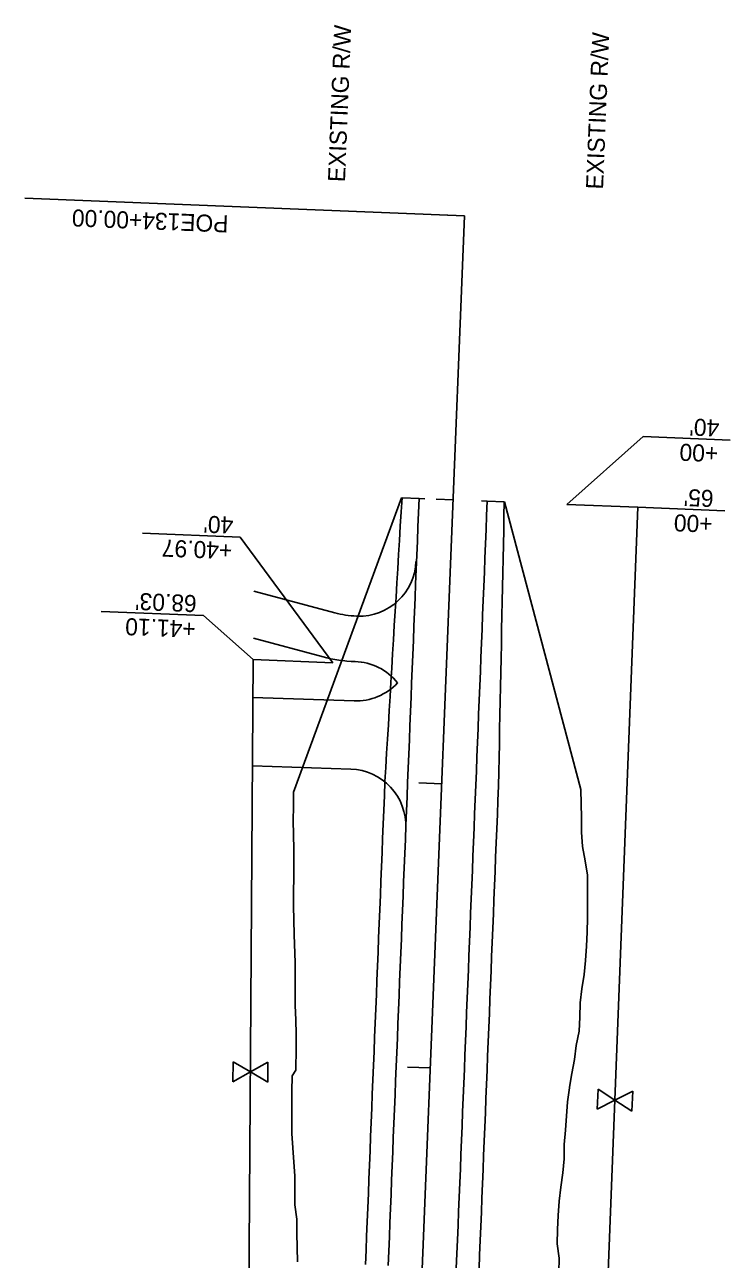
# Model space of a CAD drawing. Extents: x 634057 to 641016, y 287858 to 292331.
# Drawn here: x 634188.6 to 634436.9, y 291897 to 292331.3 of the extents above; entities that cross this region are included whole.
import ezdxf

# ---------------------------------------------------------------- set-up
doc = ezdxf.new("R2010")
doc.units = 0
for name, color, linetype in [('53', 7, 'Continuous'), ('R_50 Horz Alg PC PI PT', 7, 'Continuous'), ('R_50 Horz Alg Ticks', 7, 'Continuous'), ('R_Drive', 7, 'Continuous'), ('R_Horz Alg', 7, 'Continuous'), ('R_No Plot', 7, 'Continuous'), ('R_Proposed Const Limits', 7, 'Continuous'), ('R_Proposed Road', 7, 'Continuous'), ('R_Proposed Shoulder', 7, 'Continuous'), ('R_ROW', 7, 'Continuous')]:
    doc.layers.add(name, color=color, linetype=linetype)

msp = doc.modelspace()

# ---------------------------------------------------------------- linework, layer by layer
at = {"layer": '53'}
for p, q in [((634436.9, 292185.14), (634406.28, 292186.38)), ((634434.92, 292160.33), (634404.32, 292161.54)), ((634264.41, 292151.03), (634230.05, 292152.41)), ((634251.52, 292123.41), (634215.51, 292124.86))]:
    msp.add_line(p, q, dxfattribs=at)
for points in [[(634406.28, 292186.38), (634379.34, 292162.55)], [(634264.41, 292151.03), (634297.03, 292106.77)], [(634251.52, 292123.41), (634269.02, 292108.03)]]:
    msp.add_lwpolyline(points, dxfattribs=at)
at = {"layer": 'R_50 Horz Alg PC PI PT'}
msp.add_lwpolyline([(634343.4, 292264.06), (634188.6, 292270.3)], dxfattribs=at)
at = {"layer": 'R_50 Horz Alg Ticks'}
for points in [[(634337.38, 292264.32), (634343.37, 292264.08)], [(634333.35, 292164.4), (634339.35, 292164.16)], [(634327.35, 292064.55), (634335.35, 292064.22)], [(634323.33, 291964.63), (634331.32, 291964.31)]]:
    msp.add_lwpolyline(points, dxfattribs=at)
at = {"layer": 'R_Drive'}
for p, q in [((634297.72, 292124.39), (634269.19, 292132.04)), ((634305.63, 292123.24), (634305.4, 292123.25)), ((634293.58, 292108.93), (634269.07, 292115.5)), ((634304.51, 292093.41), (634268.93, 292094.58)), ((634303.38, 292069.43), (634268.76, 292070.57))]:
    msp.add_line(p, q, dxfattribs=at)
for centre, radius, start, end in [((634306.29, 292143.23), 20, 268.0998, 357.8615), ((634306.52, 292157.23), 34, 254.9972, 268.0998), ((634306.52, 292157.23), 50, 254.9972, 268.0998), ((634304.2, 292087.27), 20, 38.6845, 88.0998), ((634305.17, 292113.4), 20, 268.1082, 317.0537), ((634302.72, 292049.44), 20, 357.8615, 88.1082)]:
    msp.add_arc(centre, radius, start, end, dxfattribs=at)
at = {"layer": 'R_Horz Alg'}
msp.add_line((634328.23, 291887.62), (634343.4, 292264.06), dxfattribs=at)
at = {"layer": 'R_Proposed Const Limits'}
for points in [[(634283.19, 292061.32), (634321.19, 292164.86)], [(634357.49, 292163.4), (634384.25, 292062.26)], [(634384.25, 292062.26), (634384.49, 292052.24), (634384.49, 292047.23), (634384.92, 292042.21), (634385.8, 292037.17), (634386.62, 292032.14), (634386.69, 292027.13), (634386.67, 292022.12), (634386.63, 292017.12), (634386.54, 292012.12), (634386.33, 292007.13), (634385.91, 292002.14), (634385.5, 291997.15), (634384.64, 291992.18), (634384.07, 291987.2), (634383.96, 291982.2), (634383.75, 291977.21), (634382.63, 291972.25), (634382.04, 291967.27), (634381.11, 291962.3), (634380.34, 291957.6)], [(634283.99, 291963.49), (634284.08, 291971.21), (634284.11, 291976.22), (634284.06, 291981.22), (634283.72, 291986.24), (634283.73, 291996.25), (634283.74, 292001.25), (634283.46, 292011.27), (634283.26, 292016.28), (634283.14, 292021.29), (634283.24, 292026.29), (634283.28, 292031.29), (634283.32, 292041.3), (634283.23, 292046.31), (634283.1, 292051.32), (634283.14, 292056.32), (634283.19, 292061.32)], [(634284.56, 291896.13), (634284.47, 291901.14), (634284.35, 291906.15), (634284.39, 291911.15), (634283.68, 291916.18), (634283.62, 291921.19), (634283.7, 291926.19), (634283, 291936.23), (634282.63, 291941.25), (634282.61, 291946.25), (634282.66, 291956.26), (634282.72, 291961.26), (634282.73, 291961.52), (634282.73, 291961.53), (634283.99, 291963.49)], [(634380.34, 291957.6), (634380.3, 291957.33), (634379.61, 291952.35), (634378.9, 291942.37), (634378.45, 291937.39), (634378.48, 291932.38), (634377.91, 291927.4), (634377.22, 291922.42), (634376.72, 291917.44), (634376.37, 291912.45), (634376.05, 291907.46), (634376.01, 291902.46), (634376.65, 291897.43), (634376.58, 291892.43)]]:
    msp.add_lwpolyline(points, dxfattribs=at)
at = {"layer": 'R_Proposed Road'}
for points in [[(634316.51, 291894.85), (634316.71, 291899.84), (634316.92, 291904.84), (634317.12, 291909.83), (634317.32, 291914.83), (634317.52, 291919.83), (634317.72, 291924.82), (634317.92, 291929.82), (634318.12, 291934.81), (634318.32, 291939.81), (634318.53, 291944.81), (634318.73, 291949.8), (634318.93, 291954.8), (634319.13, 291959.79), (634319.33, 291964.79), (634319.53, 291969.78), (634319.73, 291974.78), (634319.93, 291979.78), (634320.14, 291984.77), (634320.34, 291989.77), (634320.54, 291994.76), (634320.74, 291999.76), (634320.94, 292004.76), (634321.14, 292009.75), (634321.34, 292014.75), (634321.54, 292019.74), (634321.75, 292024.74), (634321.95, 292029.74), (634322.15, 292034.73), (634322.35, 292039.73), (634322.55, 292044.72), (634322.75, 292049.72), (634322.95, 292054.72), (634323.15, 292059.71), (634323.36, 292064.71), (634323.56, 292069.7), (634323.76, 292074.7), (634323.96, 292079.7), (634324.16, 292084.69), (634324.36, 292089.69), (634324.56, 292094.68), (634324.76, 292099.68), (634324.97, 292104.68), (634325.17, 292109.67), (634325.37, 292114.67), (634325.57, 292119.66), (634325.77, 292124.66), (634325.97, 292129.66), (634326.17, 292134.65), (634326.37, 292139.65), (634326.58, 292144.64), (634326.78, 292149.64), (634326.98, 292154.63), (634327.18, 292159.63), (634327.38, 292164.63), (634329.38, 292164.55)], [(634340.49, 291893.88), (634340.69, 291898.88), (634340.9, 291903.87), (634341.1, 291908.87), (634341.3, 291913.86), (634341.5, 291918.86), (634341.7, 291923.86), (634341.9, 291928.85), (634342.1, 291933.85), (634342.3, 291938.84), (634342.51, 291943.84), (634342.71, 291948.84), (634342.91, 291953.83), (634343.11, 291958.83), (634343.31, 291963.82), (634343.51, 291968.82), (634343.71, 291973.81), (634343.91, 291978.81), (634344.12, 291983.81), (634344.32, 291988.8), (634344.52, 291993.8), (634344.72, 291998.79), (634344.92, 292003.79), (634345.12, 292008.79), (634345.32, 292013.78), (634345.52, 292018.78), (634345.73, 292023.77), (634345.93, 292028.77), (634346.13, 292033.77), (634346.33, 292038.76), (634346.53, 292043.76), (634346.73, 292048.75), (634346.93, 292053.75), (634347.13, 292058.75), (634347.34, 292063.74), (634347.54, 292068.74), (634347.74, 292073.73), (634347.94, 292078.73), (634348.14, 292083.73), (634348.34, 292088.72), (634348.54, 292093.72), (634348.74, 292098.71), (634348.95, 292103.71), (634349.15, 292108.71), (634349.35, 292113.7), (634349.55, 292118.7), (634349.75, 292123.69), (634349.95, 292128.69), (634350.15, 292133.69), (634350.35, 292138.68), (634350.56, 292143.68), (634350.76, 292148.67), (634350.96, 292153.67), (634351.16, 292158.66), (634351.36, 292163.66), (634349.36, 292163.74)]]:
    msp.add_lwpolyline(points, dxfattribs=at)
at = {"layer": 'R_Proposed Shoulder'}
for points in [[(634308.52, 291895.17), (634308.72, 291900.16), (634308.92, 291905.16), (634309.12, 291910.16), (634309.32, 291915.15), (634309.53, 291920.15), (634309.73, 291925.14), (634309.93, 291930.14), (634310.13, 291935.14), (634310.33, 291940.13), (634310.53, 291945.13), (634310.73, 291950.12), (634310.93, 291955.12), (634311.14, 291960.11), (634311.34, 291965.11), (634311.54, 291970.11), (634311.74, 291975.1), (634311.94, 291980.1), (634312.14, 291985.09), (634312.34, 291990.09), (634312.54, 291995.09), (634312.75, 292000.08), (634312.95, 292005.08), (634313.15, 292010.07), (634313.35, 292015.07), (634313.55, 292020.07), (634313.75, 292025.06), (634313.95, 292030.06), (634314.15, 292035.05), (634314.36, 292040.05), (634314.56, 292045.05), (634314.76, 292050.04), (634314.96, 292055.04), (634315.16, 292060.03), (634315.36, 292065.03), (634315.66, 292070.02), (634315.96, 292075.01), (634316.27, 292080.01), (634316.57, 292085), (634316.87, 292089.99), (634317.17, 292094.98), (634317.47, 292099.97), (634317.77, 292104.97), (634318.07, 292109.96), (634318.37, 292114.95), (634318.67, 292119.94), (634318.98, 292124.93), (634319.28, 292129.92), (634319.58, 292134.92), (634319.88, 292139.91), (634320.18, 292144.9), (634320.48, 292149.89), (634320.78, 292154.88), (634321.08, 292159.88), (634321.38, 292164.87), (634327.38, 292164.63)], [(634348.49, 291893.56), (634348.69, 291898.55), (634348.89, 291903.55), (634349.09, 291908.55), (634349.29, 291913.54), (634349.49, 291918.54), (634349.69, 291923.53), (634349.9, 291928.53), (634350.1, 291933.53), (634350.3, 291938.52), (634350.5, 291943.52), (634350.7, 291948.51), (634350.9, 291953.51), (634351.1, 291958.5), (634351.3, 291963.5), (634351.51, 291968.5), (634351.71, 291973.49), (634351.91, 291978.49), (634352.11, 291983.48), (634352.31, 291988.48), (634352.51, 291993.48), (634352.71, 291998.47), (634352.91, 292003.47), (634353.12, 292008.46), (634353.32, 292013.46), (634353.52, 292018.46), (634353.72, 292023.45), (634353.92, 292028.45), (634354.12, 292033.44), (634354.32, 292038.44), (634354.52, 292043.44), (634354.73, 292048.43), (634354.93, 292053.43), (634355.13, 292058.42), (634355.33, 292063.42), (634355.43, 292068.42), (634355.53, 292073.42), (634355.63, 292078.42), (634355.73, 292083.42), (634355.84, 292088.42), (634355.94, 292093.42), (634356.04, 292098.42), (634356.14, 292103.42), (634356.24, 292108.42), (634356.34, 292113.42), (634356.44, 292118.42), (634356.55, 292123.42), (634356.65, 292128.42), (634356.75, 292133.42), (634356.85, 292138.42), (634356.95, 292143.42), (634357.05, 292148.42), (634357.15, 292153.42), (634357.25, 292158.42), (634357.36, 292163.42), (634351.36, 292163.66)]]:
    msp.add_lwpolyline(points, dxfattribs=at)
at = {"layer": 'R_ROW'}
for p, q in [((634269.02, 292108.03), (634297.03, 292106.77)), ((634261.87, 291959.42), (634261.92, 291966.49)), ((634261.92, 291966.49), (634268.02, 291962.91)), ((634268.02, 291962.91), (634274.17, 291966.39)), ((634274.17, 291966.39), (634274.11, 291959.32)), ((634268.02, 291962.91), (634261.87, 291959.42)), ((634274.11, 291959.32), (634268.02, 291962.91)), ((634389.99, 291949.75), (634390.36, 291956.81)), ((634396.29, 291952.96), (634389.99, 291949.75)), ((634390.36, 291956.81), (634396.29, 291952.96)), ((634396.29, 291952.96), (634402.59, 291956.16)), ((634402.22, 291949.1), (634396.29, 291952.96)), ((634402.59, 291956.16), (634402.22, 291949.1))]:
    msp.add_line(p, q, dxfattribs=at)
for points in [[(634379.34, 292162.55), (634404.32, 292161.54)], [(634404.32, 292161.54), (634388.9, 291762.53), (634380.33, 291604.07)], [(634269.02, 292108.03), (634267.36, 291866.68), (634250.58, 291620.66)]]:
    msp.add_lwpolyline(points, dxfattribs=at)

# ---------------------------------------------------------------- texts
at = {"layer": '53'}
for s, rotation, p in [('EXISTING R/W', 87.6932, (634301.3, 292275.84)), ('EXISTING R/W', 87.6932, (634392.1, 292273.26)), ("40'  ", 177.6932, (634433.13, 292192.37)), ('+00 ', 177.6932, (634432.76, 292183.38)), ("65'  ", 177.6932, (634431.14, 292167.56)), ("40'  ", 177.6932, (634262.12, 292158.19)), ('+00 ', 177.6932, (634430.78, 292158.56)), ('+40.97 ', 177.6932, (634261.76, 292149.2)), ("68.03'  ", 177.6932, (634249.23, 292130.58)), ('+41.10 ', 177.6932, (634248.86, 292121.58))]:
    msp.add_text(s, height=6, rotation=rotation, dxfattribs=at).set_placement(p)
at = {"layer": 'R_50 Horz Alg PC PI PT'}
msp.add_text('POE134+00.00', height=6, rotation=177.6932, dxfattribs=at).set_placement((634260.4, 292264.15))
at = {"layer": 'R_No Plot'}
for p in [(634336.04, 292080.17), (634331.23, 291960.92), (634331.23, 291960.92), (634331.23, 291960.92), (634331.23, 291960.92), (634331.23, 291960.92), (634331.23, 291960.92), (634331.23, 291960.92), (634331.23, 291960.92)]:
    msp.add_text('+', height=0.1, rotation=87.6932, dxfattribs=at).set_placement(p)

doc.saveas('drawing.dxf')
